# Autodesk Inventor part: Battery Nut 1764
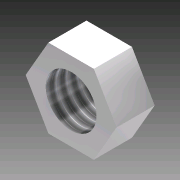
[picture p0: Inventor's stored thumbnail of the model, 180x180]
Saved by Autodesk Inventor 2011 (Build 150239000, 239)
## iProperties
Created: 2008-01
Part Number: Battery Nut 1764
Document SubType Name: Modeling
Designer: rlindsay
Density: 1 g/cm^3
Author: rlindsay
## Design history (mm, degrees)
sketch "Sketch1"
  geometry: L1 (-8.51, 10.842)-(-6.237, 6.905); L2 (-6.237, 6.905)-(-8.51, 2.968); L3 (-8.51, 2.968)-(-13.056, 2.968); L4 (-13.056, 2.968)-(-15.329, 6.905); L5 (-15.329, 6.905)-(-13.056, 10.842); L6 (-13.056, 10.842)-(-8.51, 10.842); C1 r 2.54 at (-10.783, 6.905); 1 further point
  constraints: 12 end point, 1 centre point, 1 coincident, 13 other
  dimensions: "d0" = 7.874 distance between parallel lines of L3 L6; "d1" = 5.08 diameter of C1
extrude "Extrusion1" new body sketch "Sketch1" distance "d2" = 3.81; taper "d3" = 0 deg
thread "Thread1" dims "d4" = 25.4, "d5" = 0
body "Solid1"
